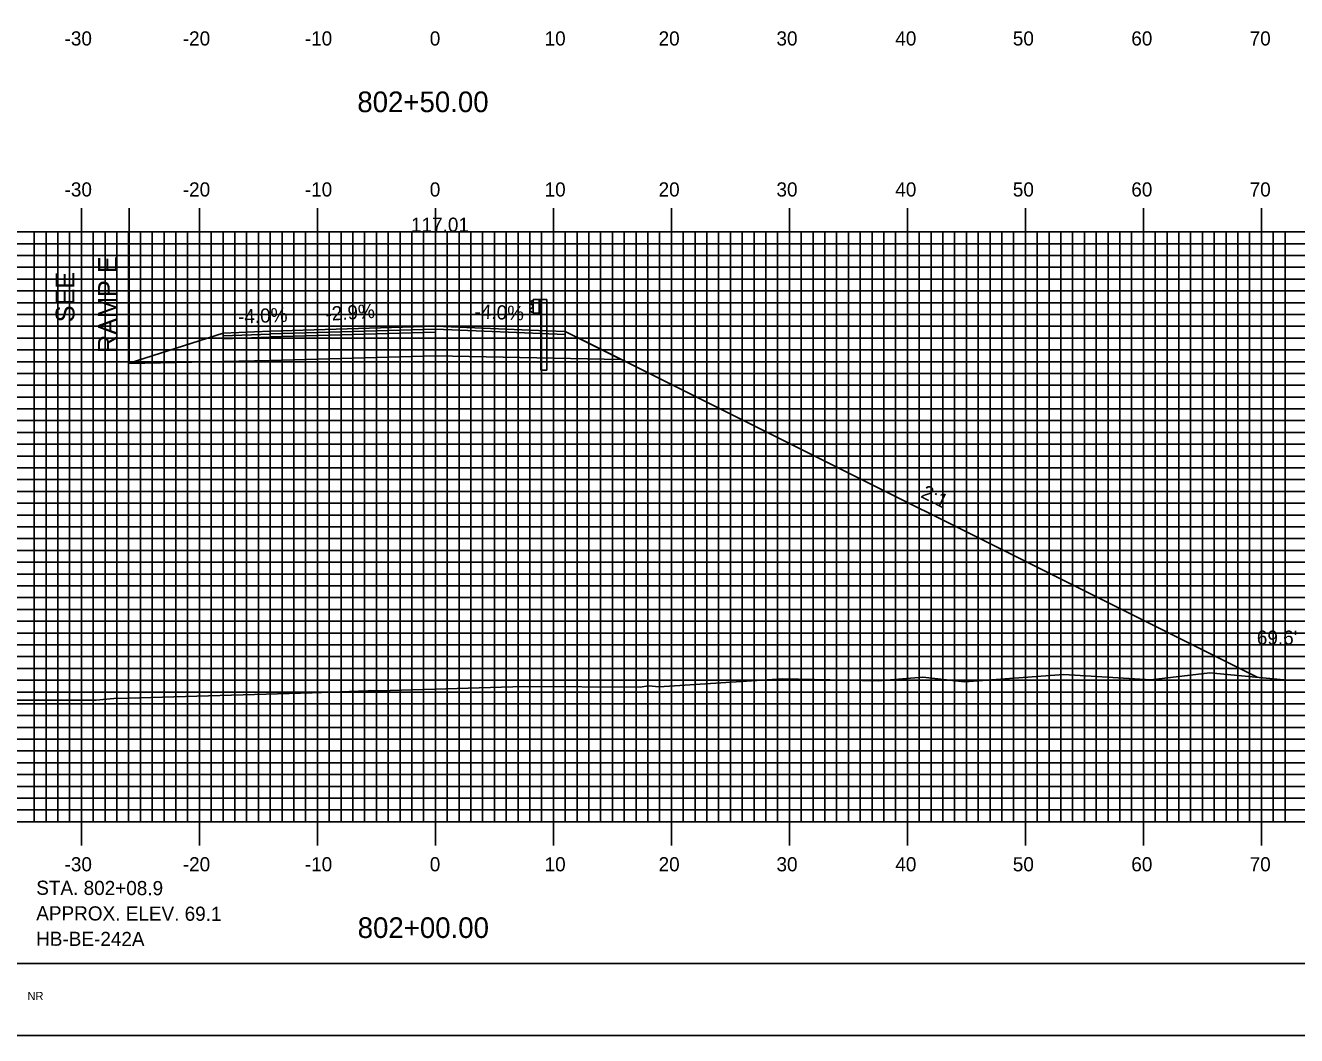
# Model space of a CAD drawing. Extents: x -302 to 42, y -1658 to -1438.
# Drawn here: x -170.6 to -62.9, y -1657.7 to -1572.1 of the extents above; entities that cross this region are included whole.
import ezdxf

# ---------------------------------------------------------------- set-up
doc = ezdxf.new("R2010")
doc.units = 0
for name, color, linetype in [('ANNOTATION', 7, 'Continuous'), ('BORDER', 7, 'Continuous'), ('BORING - NO REFUSAL', 7, 'Continuous'), ('BORING - REFUSAL', 7, 'Continuous'), ('D_Guardrail_Beam_Rt', 7, 'Continuous'), ('D_Roadway_Centerline_Text', 7, 'Continuous'), ('D_Roadway_Edge_Shoulder', 7, 'Continuous'), ('D_Roadway_Pavement', 7, 'Continuous'), ('D_Roadway_SlopeLines', 7, 'Continuous'), ('D_Roadway_SubGrade', 7, 'Continuous'), ('D_Text_Standard', 7, 'Continuous'), ('H_V ANNOTATION', 7, 'Continuous'), ('MAJOR', 7, 'Continuous'), ('MINOR', 7, 'Continuous'), ('PLOT BOUNDARY', 7, 'Continuous'), ('S_Roadway_Centerline', 7, 'Continuous')]:
    doc.layers.add(name, color=color, linetype=linetype)

msp = doc.modelspace()

# ---------------------------------------------------------------- linework, layer by layer
at = {"layer": 'BORDER'}
msp.add_lwpolyline([(-285.49, -1651.6), (34.51, -1651.6), (34.51, -1441.6), (-285.49, -1441.6)], close=True, dxfattribs=at)
at = {"layer": 'D_Guardrail_Beam_Rt'}
for p, q in [((-127.62, -1595.33), (-126.93, -1595.33)), ((-127.62, -1596.5), (-127.62, -1595.33)), ((-127.1, -1595.33), (-127.1, -1596.5)), ((-127, -1595.33), (-127, -1596.5)), ((-126.93, -1595.33), (-126.46, -1595.33)), ((-126.93, -1595.33), (-126.93, -1596.5)), ((-126.46, -1595.33), (-126.46, -1601.33)), ((-127.71, -1595.44), (-127.85, -1595.54)), ((-127.85, -1595.68), (-127.66, -1595.82)), ((-127.66, -1596.02), (-127.85, -1596.15)), ((-127.85, -1596.3), (-127.71, -1596.4)), ((-127.62, -1595.42), (-127.7, -1595.43)), ((-127.7, -1596.4), (-127.62, -1596.42)), ((-127.63, -1595.88), (-127.63, -1595.95)), ((-126.93, -1596.5), (-127.62, -1596.5)), ((-126.95, -1601.33), (-126.95, -1596.5)), ((-126.95, -1601.33), (-126.46, -1601.33))]:
    msp.add_line(p, q, dxfattribs=at)
for centre, major_axis, start_param, end_param in [((-127.8, -1595.61), (-0.0877, 0), 5.323254, 7.243116), ((-127.8, -1596.22), (-0.0877, 0), 5.323254, 7.243116), ((-127.69, -1595.47), (-0.0417, 0), 4.907132, 5.323254), ((-127.69, -1596.36), (-0.0417, 0), 0.959931, 1.376053), ((-127.7, -1595.88), (0.0789, 0), 0, 0.959931), ((-127.7, -1595.95), (0.0789, 0), 5.323254, 6.283185)]:
    msp.add_ellipse(centre, major_axis=major_axis, ratio=0.995501, start_param=start_param, end_param=end_param, dxfattribs=at)
at = {"layer": 'D_Roadway_Edge_Shoulder'}
for points in [[(-149.89, -1598.01), (-153.89, -1598.17), (-153.89, -1598.42), (-149.89, -1598.26)], [(-135.89, -1597.6), (-127.89, -1597.92), (-127.89, -1597.92), (-124.89, -1598.04), (-124.89, -1598.29), (-135.89, -1597.85)]]:
    msp.add_lwpolyline(points, close=True, dxfattribs=at)
at = {"layer": 'D_Roadway_Pavement'}
msp.add_lwpolyline([(-149.89, -1598.26), (-153.89, -1598.42), (-153.89, -1598.67), (-149.89, -1598.51)], close=True, dxfattribs=at)
msp.add_lwpolyline([(-135.89, -1597.85), (-135.89, -1598.1)], dxfattribs=at)
msp.add_lwpolyline([(-135.89, -1597.85), (-135.89, -1598.1)], dxfattribs=at)
at = {"layer": 'D_Roadway_SlopeLines'}
for p, q in [((-153.89, -1598.17), (-161.84, -1600.74)), ((-135.89, -1597.6), (-149.89, -1598.01)), ((-135.89, -1597.85), (-149.89, -1598.25)), ((-135.89, -1598.1), (-149.89, -1598.5)), ((-153.89, -1600.59), (-161.84, -1600.75)), ((-135.89, -1600.1), (-149.89, -1600.51))]:
    msp.add_line(p, q, dxfattribs=at)
msp.add_lwpolyline([(-124.89, -1598.04), (-122.89, -1599.04), (-66.26, -1627.35)], dxfattribs=at)
at = {"layer": 'D_Roadway_SubGrade'}
for p, q in [((-161.84, -1587.6), (-161.84, -1600.74)), ((-153.89, -1600.59), (-149.89, -1600.51))]:
    msp.add_line(p, q, dxfattribs=at)
msp.add_lwpolyline([(-135.89, -1598.1), (-135.89, -1597.85), (-124.89, -1598.29), (-124.89, -1598.04), (-120.14, -1600.41), (-135.89, -1600.1)], close=True, dxfattribs=at)
at = {"layer": 'MAJOR'}
for p, q in [((-165.89, -1587.6), (-165.89, -1589.6)), ((-155.89, -1587.6), (-155.89, -1589.6)), ((-145.89, -1587.6), (-145.89, -1589.6)), ((-135.89, -1587.6), (-135.89, -1589.6)), ((-125.89, -1587.6), (-125.89, -1589.6)), ((-115.89, -1587.6), (-115.89, -1589.6)), ((-105.89, -1587.6), (-105.89, -1589.6)), ((-95.89, -1587.6), (-95.89, -1589.6)), ((-85.89, -1587.6), (-85.89, -1589.6)), ((-75.89, -1587.6), (-75.89, -1589.6)), ((-65.89, -1587.6), (-65.89, -1589.6)), ((-275.89, -1589.6), (4.11, -1589.6)), ((-275.89, -1589.6), (4.11, -1589.6)), ((-165.89, -1639.6), (-165.89, -1589.6)), ((-155.89, -1639.6), (-155.89, -1589.6)), ((-145.89, -1639.6), (-145.89, -1589.6)), ((-135.89, -1639.6), (-135.89, -1589.6)), ((-125.89, -1639.6), (-125.89, -1589.6)), ((-115.89, -1639.6), (-115.89, -1589.6)), ((-105.89, -1639.6), (-105.89, -1589.6)), ((-95.89, -1639.6), (-95.89, -1589.6)), ((-85.89, -1639.6), (-85.89, -1589.6)), ((-75.89, -1639.6), (-75.89, -1589.6)), ((-65.89, -1639.6), (-65.89, -1589.6)), ((-275.89, -1594.6), (4.11, -1594.6)), ((-275.89, -1599.6), (4.11, -1599.6)), ((-275.89, -1604.6), (4.11, -1604.6)), ((-275.89, -1609.6), (4.11, -1609.6)), ((-275.89, -1614.6), (4.11, -1614.6)), ((-275.89, -1619.6), (4.11, -1619.6)), ((-275.89, -1624.6), (4.11, -1624.6)), ((-275.89, -1629.6), (4.11, -1629.6)), ((-275.89, -1634.6), (4.11, -1634.6)), ((-275.89, -1639.6), (4.11, -1639.6)), ((-275.89, -1639.6), (4.11, -1639.6)), ((-165.89, -1641.61), (-165.89, -1639.6)), ((-155.89, -1641.61), (-155.89, -1639.6)), ((-145.89, -1641.61), (-145.89, -1639.6)), ((-135.89, -1641.61), (-135.89, -1639.6)), ((-125.89, -1641.61), (-125.89, -1639.6)), ((-115.89, -1641.61), (-115.89, -1639.6)), ((-105.89, -1641.61), (-105.89, -1639.6)), ((-95.89, -1641.61), (-95.89, -1639.6)), ((-85.89, -1641.61), (-85.89, -1639.6)), ((-75.89, -1641.61), (-75.89, -1639.6)), ((-65.89, -1641.61), (-65.89, -1639.6))]:
    msp.add_line(p, q, dxfattribs=at)
at = {"layer": 'MINOR'}
for p, q in [((-169.89, -1639.6), (-169.89, -1589.6)), ((-168.89, -1639.6), (-168.89, -1589.6)), ((-167.89, -1639.6), (-167.89, -1589.6)), ((-166.89, -1639.6), (-166.89, -1589.6)), ((-164.89, -1639.6), (-164.89, -1589.6)), ((-163.89, -1639.6), (-163.89, -1589.6)), ((-162.89, -1639.6), (-162.89, -1589.6)), ((-161.89, -1639.6), (-161.89, -1589.6)), ((-160.89, -1639.6), (-160.89, -1589.6)), ((-159.89, -1639.6), (-159.89, -1589.6)), ((-158.89, -1639.6), (-158.89, -1589.6)), ((-157.89, -1639.6), (-157.89, -1589.6)), ((-156.89, -1639.6), (-156.89, -1589.6)), ((-154.89, -1639.6), (-154.89, -1589.6)), ((-153.89, -1639.6), (-153.89, -1589.6)), ((-152.89, -1639.6), (-152.89, -1589.6)), ((-151.89, -1639.6), (-151.89, -1589.6)), ((-150.89, -1639.6), (-150.89, -1589.6)), ((-149.89, -1639.6), (-149.89, -1589.6)), ((-148.89, -1639.6), (-148.89, -1589.6)), ((-147.89, -1639.6), (-147.89, -1589.6)), ((-146.89, -1639.6), (-146.89, -1589.6)), ((-144.89, -1639.6), (-144.89, -1589.6)), ((-143.89, -1639.6), (-143.89, -1589.6)), ((-142.89, -1639.6), (-142.89, -1589.6)), ((-141.89, -1639.6), (-141.89, -1589.6)), ((-140.89, -1639.6), (-140.89, -1589.6)), ((-139.89, -1639.6), (-139.89, -1589.6)), ((-138.89, -1639.6), (-138.89, -1589.6)), ((-137.89, -1639.6), (-137.89, -1589.6)), ((-136.89, -1639.6), (-136.89, -1589.6)), ((-134.89, -1639.6), (-134.89, -1589.6)), ((-133.89, -1639.6), (-133.89, -1589.6)), ((-132.89, -1639.6), (-132.89, -1589.6)), ((-131.89, -1639.6), (-131.89, -1589.6)), ((-130.89, -1639.6), (-130.89, -1589.6)), ((-129.89, -1639.6), (-129.89, -1589.6)), ((-128.89, -1639.6), (-128.89, -1589.6)), ((-127.89, -1639.6), (-127.89, -1589.6)), ((-126.89, -1639.6), (-126.89, -1589.6)), ((-124.89, -1639.6), (-124.89, -1589.6)), ((-123.89, -1639.6), (-123.89, -1589.6)), ((-122.89, -1639.6), (-122.89, -1589.6)), ((-121.89, -1639.6), (-121.89, -1589.6)), ((-120.89, -1639.6), (-120.89, -1589.6)), ((-119.89, -1639.6), (-119.89, -1589.6)), ((-118.89, -1639.6), (-118.89, -1589.6)), ((-117.89, -1639.6), (-117.89, -1589.6)), ((-116.89, -1639.6), (-116.89, -1589.6)), ((-114.89, -1639.6), (-114.89, -1589.6)), ((-113.89, -1639.6), (-113.89, -1589.6)), ((-112.89, -1639.6), (-112.89, -1589.6)), ((-111.89, -1639.6), (-111.89, -1589.6)), ((-110.89, -1639.6), (-110.89, -1589.6)), ((-109.89, -1639.6), (-109.89, -1589.6)), ((-108.89, -1639.6), (-108.89, -1589.6)), ((-107.89, -1639.6), (-107.89, -1589.6)), ((-106.89, -1639.6), (-106.89, -1589.6)), ((-104.89, -1639.6), (-104.89, -1589.6)), ((-103.89, -1639.6), (-103.89, -1589.6)), ((-102.89, -1639.6), (-102.89, -1589.6)), ((-101.89, -1639.6), (-101.89, -1589.6)), ((-100.89, -1639.6), (-100.89, -1589.6)), ((-99.89, -1639.6), (-99.89, -1589.6)), ((-98.89, -1639.6), (-98.89, -1589.6)), ((-97.89, -1639.6), (-97.89, -1589.6)), ((-96.89, -1639.6), (-96.89, -1589.6)), ((-94.89, -1639.6), (-94.89, -1589.6)), ((-93.89, -1639.6), (-93.89, -1589.6)), ((-92.89, -1639.6), (-92.89, -1589.6)), ((-91.89, -1639.6), (-91.89, -1589.6)), ((-90.89, -1639.6), (-90.89, -1589.6)), ((-89.89, -1639.6), (-89.89, -1589.6)), ((-88.89, -1639.6), (-88.89, -1589.6)), ((-87.89, -1639.6), (-87.89, -1589.6)), ((-86.89, -1639.6), (-86.89, -1589.6)), ((-84.89, -1639.6), (-84.89, -1589.6)), ((-83.89, -1639.6), (-83.89, -1589.6)), ((-82.89, -1639.6), (-82.89, -1589.6)), ((-81.89, -1639.6), (-81.89, -1589.6)), ((-80.89, -1639.6), (-80.89, -1589.6)), ((-79.89, -1639.6), (-79.89, -1589.6)), ((-78.89, -1639.6), (-78.89, -1589.6)), ((-77.89, -1639.6), (-77.89, -1589.6)), ((-76.89, -1639.6), (-76.89, -1589.6)), ((-74.89, -1639.6), (-74.89, -1589.6)), ((-73.89, -1639.6), (-73.89, -1589.6)), ((-72.89, -1639.6), (-72.89, -1589.6)), ((-71.89, -1639.6), (-71.89, -1589.6)), ((-70.89, -1639.6), (-70.89, -1589.6)), ((-69.89, -1639.6), (-69.89, -1589.6)), ((-68.89, -1639.6), (-68.89, -1589.6)), ((-67.89, -1639.6), (-67.89, -1589.6)), ((-66.89, -1639.6), (-66.89, -1589.6)), ((-64.89, -1639.6), (-64.89, -1589.6)), ((-63.89, -1639.6), (-63.89, -1589.6)), ((-275.89, -1590.6), (4.11, -1590.6)), ((-275.89, -1591.6), (4.11, -1591.6)), ((-275.89, -1592.6), (4.11, -1592.6)), ((-275.89, -1593.6), (4.11, -1593.6)), ((-275.89, -1595.6), (4.11, -1595.6)), ((-275.89, -1596.6), (4.11, -1596.6)), ((-275.89, -1597.6), (4.11, -1597.6)), ((-275.89, -1598.6), (4.11, -1598.6)), ((-275.89, -1600.6), (4.11, -1600.6)), ((-275.89, -1601.6), (4.11, -1601.6)), ((-275.89, -1602.6), (4.11, -1602.6)), ((-275.89, -1603.6), (4.11, -1603.6)), ((-275.89, -1605.6), (4.11, -1605.6)), ((-275.89, -1606.6), (4.11, -1606.6)), ((-275.89, -1607.6), (4.11, -1607.6)), ((-275.89, -1608.6), (4.11, -1608.6)), ((-275.89, -1610.6), (4.11, -1610.6)), ((-275.89, -1611.6), (4.11, -1611.6)), ((-275.89, -1612.6), (4.11, -1612.6)), ((-275.89, -1613.6), (4.11, -1613.6)), ((-275.89, -1615.6), (4.11, -1615.6)), ((-275.89, -1616.6), (4.11, -1616.6)), ((-275.89, -1617.6), (4.11, -1617.6)), ((-275.89, -1618.6), (4.11, -1618.6)), ((-275.89, -1620.6), (4.11, -1620.6)), ((-275.89, -1621.6), (4.11, -1621.6)), ((-275.89, -1622.6), (4.11, -1622.6)), ((-275.89, -1623.6), (4.11, -1623.6)), ((-275.89, -1625.6), (4.11, -1625.6)), ((-275.89, -1626.6), (4.11, -1626.6)), ((-275.89, -1627.6), (4.11, -1627.6)), ((-275.89, -1628.6), (4.11, -1628.6)), ((-275.89, -1630.6), (4.11, -1630.6)), ((-275.89, -1631.6), (4.11, -1631.6)), ((-275.89, -1632.6), (4.11, -1632.6)), ((-275.89, -1633.6), (4.11, -1633.6)), ((-275.89, -1635.6), (4.11, -1635.6)), ((-275.89, -1636.6), (4.11, -1636.6)), ((-275.89, -1637.6), (4.11, -1637.6)), ((-275.89, -1638.6), (4.11, -1638.6))]:
    msp.add_line(p, q, dxfattribs=at)
at = {"layer": 'PLOT BOUNDARY'}
msp.add_lwpolyline([(-301.68, -1657.72), (38.32, -1657.72), (38.32, -1437.72), (-301.68, -1437.72)], close=True, dxfattribs=at)
at = {"layer": 'S_Roadway_Centerline'}
msp.add_lwpolyline([(-184.52, -1629.3), (-164.65, -1629.28), (-163.15, -1629.15), (-161.97, -1629.13), (-146.34, -1628.67), (-141.63, -1628.5), (-141.41, -1628.47), (-140.66, -1628.51), (-128.4, -1628.14), (-118.54, -1628.18), (-117.84, -1628.08), (-116.94, -1628.15), (-106.47, -1627.49), (-98.38, -1627.66), (-94.59, -1627.34), (-91.05, -1627.74), (-82.63, -1627.13), (-75.25, -1627.57), (-70.26, -1626.97), (-64, -1627.57), (-53.46, -1627.62)], dxfattribs=at)

# ---------------------------------------------------------------- texts
at = {"layer": 'ANNOTATION'}
for s, height, rotation, p in [('RAMP E', 1.6, 90, (-162.88, -1599.87)), ('SEE', 1.6, 90, (-166.48, -1597.26)), ('-4.0%', 1.2, 2.2236, (-152.6, -1597.38)), ('-2.9%', 1.2, 3.4884, (-145.18, -1597.15)), ('-4.0%', 1.2, 357.7094, (-132.6, -1596.93)), ('2:1', 1.2, 333.4349, (-94.84, -1612.07))]:
    msp.add_text(s, height=height, rotation=rotation, dxfattribs=at).set_placement(p)
at = {"layer": 'BORING - NO REFUSAL'}
msp.add_text('NR', height=0.7, dxfattribs=at).set_placement((-170.46, -1654.72))
at = {"layer": 'BORING - REFUSAL'}
for s, p in [('STA. 802+08.9', (-169.72, -1645.79)), ('APPROX. ELEV. 69.1', (-169.72, -1647.95)), ('HB-BE-242A', (-169.73, -1650.11))]:
    msp.add_text(s, height=1.2, rotation=359.8142, dxfattribs=at).set_placement(p)
at = {"layer": 'D_Roadway_Centerline_Text'}
msp.add_text('117.01', height=1.2, dxfattribs=at).set_placement((-137.96, -1589.59))
at = {"layer": 'D_Text_Standard'}
msp.add_text("69.6'", height=1.2, dxfattribs=at).set_placement((-66.28, -1624.59))
at = {"layer": 'H_V ANNOTATION'}
for s, height, p in [('-30', 1.2, (-167.32, -1573.8)), ('-20', 1.2, (-157.3, -1573.8)), ('-10', 1.2, (-146.96, -1573.8)), ('0', 1.2, (-136.37, -1573.8)), ('10', 1.2, (-126.64, -1573.8)), ('20', 1.2, (-116.98, -1573.8)), ('30', 1.2, (-106.99, -1573.8)), ('40', 1.2, (-96.92, -1573.8)), ('50', 1.2, (-86.96, -1573.8)), ('60', 1.2, (-76.92, -1573.8)), ('70', 1.2, (-66.89, -1573.8)), ('802+50.00', 1.75, (-142.51, -1579.45)), ('-30', 1.2, (-167.32, -1586.6)), ('-20', 1.2, (-157.3, -1586.6)), ('-10', 1.2, (-146.96, -1586.6)), ('0', 1.2, (-136.37, -1586.6)), ('10', 1.2, (-126.64, -1586.6)), ('20', 1.2, (-116.98, -1586.6)), ('30', 1.2, (-106.99, -1586.6)), ('40', 1.2, (-96.92, -1586.6)), ('50', 1.2, (-86.96, -1586.6)), ('60', 1.2, (-76.92, -1586.6)), ('70', 1.2, (-66.89, -1586.6)), ('-30', 1.2, (-167.32, -1643.8)), ('-20', 1.2, (-157.3, -1643.8)), ('-10', 1.2, (-146.96, -1643.8)), ('0', 1.2, (-136.37, -1643.8)), ('10', 1.2, (-126.64, -1643.8)), ('20', 1.2, (-116.98, -1643.8)), ('30', 1.2, (-106.99, -1643.8)), ('40', 1.2, (-96.92, -1643.8)), ('50', 1.2, (-86.96, -1643.8)), ('60', 1.2, (-76.92, -1643.8)), ('70', 1.2, (-66.89, -1643.8)), ('802+00.00', 1.75, (-142.48, -1649.45))]:
    msp.add_text(s, height=height, dxfattribs=at).set_placement(p)

doc.saveas('drawing.dxf')
